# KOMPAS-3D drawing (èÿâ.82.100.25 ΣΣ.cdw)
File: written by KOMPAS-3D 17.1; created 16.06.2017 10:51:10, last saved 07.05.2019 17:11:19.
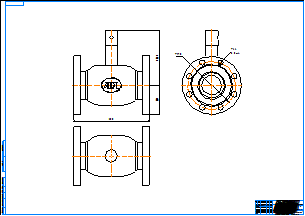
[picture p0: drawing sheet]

Sheet 1: A0, landscape

Title block, sheet 1: name: КШГ.82.100.25 фф; material: Внимание! Данный продукт является объектом авторского права ООО «Торговый Дом АДЛ». / Запрещается изменение, копирование, распространение / (в том числе путем копирования на другие сайты и ресурсы в Интернете) / или любое иное использование информации и объектов без предварительного / согласия правообладателя (ООО «Торговый Дом АДЛ»).; scale: 1:1; sheets: 1; organisation: ООО "Торговый дом АДЛ"; sheet format: A0; stored path: C:\Users\tra\Desktop\2д чертежи\Шаровые краны БИВАЛ\КШ_Бивал_серия_82_85\KOMPAS 2D\КШГ.82.100.25 фф.cdw

Views: Спереди 1, Проекционный вид 2, Проекционный вид 3
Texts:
  Klimkovich
  ADL
Dimensions and other numbers on the sheet: 300; 214,6; 115; 190; 22; 8 Отв.; 1:1; 1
